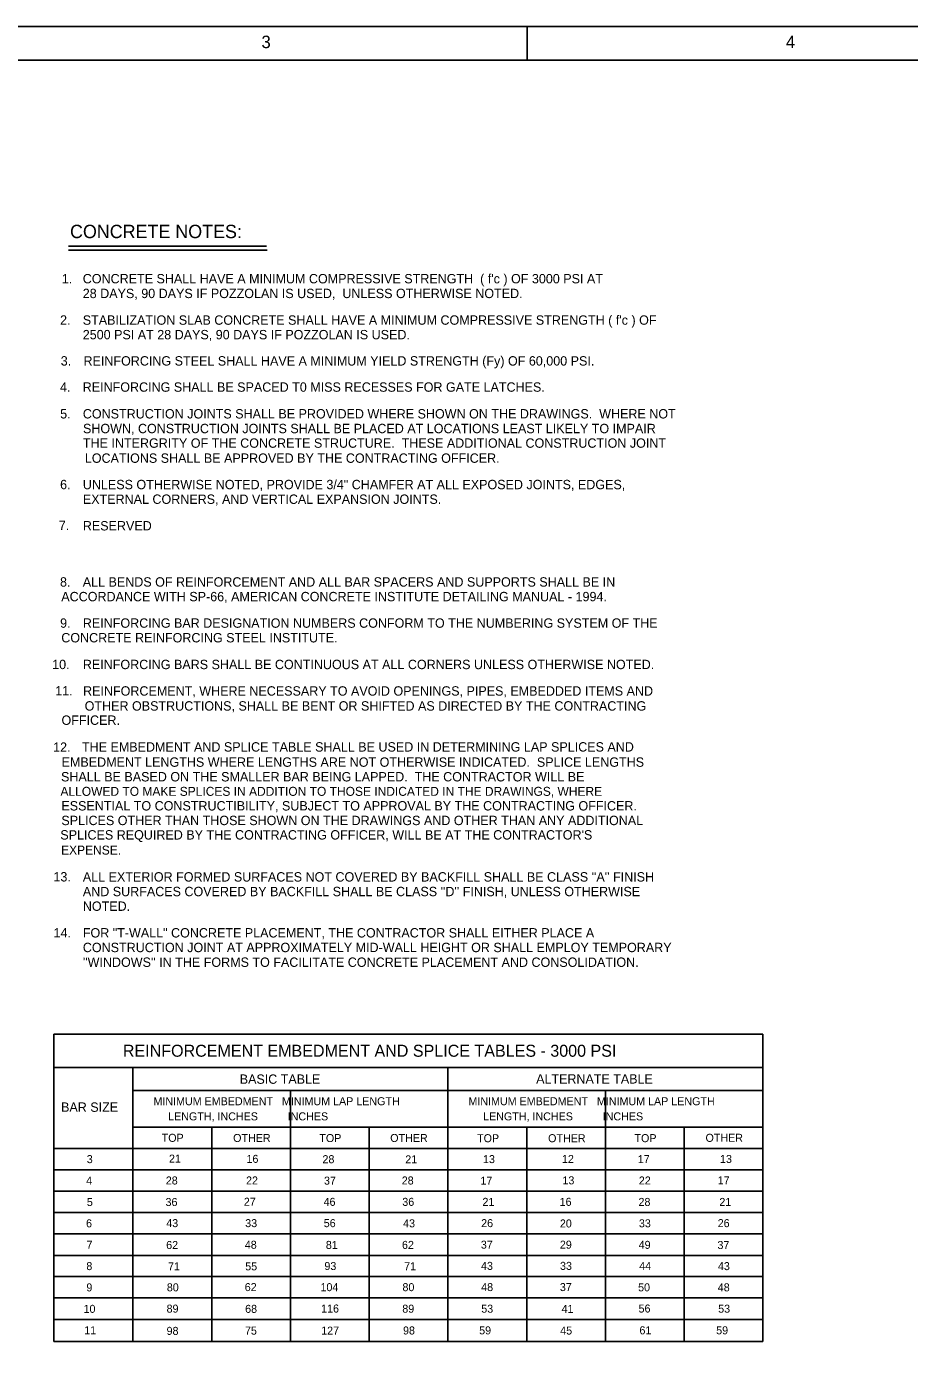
# Model space of a CAD drawing. Extents: x 22369.62 to 22373.29, y 22369.62 to 22372.46.
# Drawn here: x 22371.083 to 22372.185, y 22370.797 to 22372.455 of the extents above; entities that cross this region are included whole.
import ezdxf

# ---------------------------------------------------------------- set-up
doc = ezdxf.new("R2010")
doc.units = 0
for name, color, linetype in [('Level 1', 7, 'Continuous'), ('Level 10', 7, 'Continuous'), ('Level 2', 7, 'Continuous'), ('Level 3', 7, 'Continuous'), ('Level 4', 7, 'Continuous'), ('Level 7', 7, 'Continuous'), ('Level 9', 7, 'Continuous')]:
    doc.layers.add(name, color=color, linetype=linetype)

msp = doc.modelspace()

# ---------------------------------------------------------------- linework, layer by layer
at = {"layer": 'Level 1'}
for p, q in [((22372.0023, 22371.0269), (22371.1167, 22371.0269)), ((22372.0023, 22371.0001), (22371.1167, 22371.0001)), ((22372.0023, 22370.9735), (22371.1167, 22370.9735)), ((22372.0023, 22370.9467), (22371.1167, 22370.9467)), ((22372.0023, 22370.9198), (22371.1167, 22370.9198)), ((22372.0023, 22370.8934), (22371.1167, 22370.8934)), ((22372.0023, 22370.8668), (22371.1167, 22370.8668)), ((22372.0023, 22370.8399), (22371.1167, 22370.8399))]:
    msp.add_line(p, q, dxfattribs=at)
msp.add_lwpolyline([(22369.6213, 22372.4553), (22373.288, 22372.4553), (22373.288, 22369.6213), (22369.6213, 22369.6213)], close=True, dxfattribs=at)
at = {"layer": 'Level 10'}
for p, q in [((22371.708, 22372.4133), (22371.708, 22372.4553)), ((22371.1351, 22372.1807), (22371.3823, 22372.1807)), ((22371.1351, 22372.1757), (22371.383, 22372.1757)), ((22371.1167, 22370.8125), (22371.1167, 22371.1964)), ((22371.1167, 22371.1964), (22372.0023, 22371.1964)), ((22372.0023, 22370.8125), (22372.0023, 22371.1964)), ((22371.1167, 22371.1546), (22372.0023, 22371.1546)), ((22372.0023, 22370.8125), (22371.1167, 22370.8125))]:
    msp.add_line(p, q, dxfattribs=at)
at = {"layer": 'Level 2'}
for p, q in [((22371.2154, 22371.0802), (22372.0023, 22371.0802)), ((22371.3138, 22370.8125), (22371.3138, 22371.0802)), ((22371.5106, 22370.8125), (22371.5106, 22371.0802)), ((22371.7073, 22370.8125), (22371.7073, 22371.0802)), ((22371.904, 22370.8125), (22371.904, 22371.0802))]:
    msp.add_line(p, q, dxfattribs=at)
at = {"layer": 'Level 7'}
for p, q in [((22371.2154, 22370.8125), (22371.2154, 22371.1546)), ((22371.6089, 22370.8125), (22371.6089, 22371.1546)), ((22371.2154, 22371.1259), (22372.0023, 22371.1259)), ((22371.4122, 22370.8125), (22371.4122, 22371.1259)), ((22371.8056, 22370.8125), (22371.8056, 22371.1259)), ((22372.0023, 22371.0535), (22371.1167, 22371.0535))]:
    msp.add_line(p, q, dxfattribs=at)
at = {"layer": 'Level 9'}
msp.add_line((22369.7463, 22372.4133), (22373.017, 22372.4133), dxfattribs=at)

# ---------------------------------------------------------------- texts
at = {"layer": 'Level 1'}
for s, p in [('3', (22371.376, 22372.4283)), ('4', (22372.031, 22372.4283))]:
    msp.add_text(s, height=0.0156, dxfattribs=at).set_placement(p)
at = {"layer": 'Level 3'}
msp.add_text('CONCRETE NOTES:', height=0.016698, dxfattribs=at).set_placement((22371.1369, 22372.1909))
at = {"layer": 'Level 4'}
for s, height, p in [('1.', 0.0117, (22371.1267, 22372.1344)), ("CONCRETE SHALL HAVE A MINIMUM COMPRESSIVE STRENGTH  ( f'c ) OF 3000 PSI AT", 0.011698, (22371.1528, 22372.1344)), ('28 DAYS, 90 DAYS IF POZZOLAN IS USED,  UNLESS OTHERWISE NOTED.', 0.011698, (22371.1528, 22372.116)), ('2.', 0.0117, (22371.1245, 22372.0828)), ("STABILIZATION SLAB CONCRETE SHALL HAVE A MINIMUM COMPRESSIVE STRENGTH ( f'c ) OF", 0.011698, (22371.1528, 22372.0827)), ('2500 PSI AT 28 DAYS, 90 DAYS IF POZZOLAN IS USED.', 0.011698, (22371.1528, 22372.0645)), ('3.', 0.0117, (22371.1253, 22372.0317)), ('REINFORCING STEEL SHALL HAVE A MINIMUM YIELD STRENGTH (Fy) OF 60,000 PSI.', 0.011698, (22371.1537, 22372.0317)), ('4.', 0.0117, (22371.1244, 22371.999)), ('REINFORCING SHALL BE SPACED T0 MISS RECESSES FOR GATE LATCHES.', 0.011698, (22371.1527, 22371.999)), ('5.', 0.0117, (22371.1246, 22371.9656)), ('CONSTRUCTION JOINTS SHALL BE PROVIDED WHERE SHOWN ON THE DRAWINGS.  WHERE NOT', 0.011698, (22371.1529, 22371.9656)), ('SHOWN, CONSTRUCTION JOINTS SHALL BE PLACED AT LOCATIONS LEAST LIKELY TO IMPAIR', 0.011698, (22371.1531, 22371.9472)), ('THE INTERGRITY OF THE CONCRETE STRUCTURE.  THESE ADDITIONAL CONSTRUCTION JOINT', 0.011698, (22371.153, 22371.929)), ('LOCATIONS SHALL BE APPROVED BY THE CONTRACTING OFFICER.', 0.011698, (22371.1554, 22371.9102)), ('6.', 0.0117, (22371.1245, 22371.8772)), ('UNLESS OTHERWISE NOTED, PROVIDE 3/4" CHAMFER AT ALL EXPOSED JOINTS, EDGES,', 0.011698, (22371.1529, 22371.8772)), ('EXTERNAL CORNERS, AND VERTICAL EXPANSION JOINTS.', 0.011698, (22371.1529, 22371.8589)), ('7.', 0.0117, (22371.1229, 22371.8261)), ('RESERVED', 0.0117, (22371.1529, 22371.8257)), ('8.', 0.0117, (22371.1244, 22371.7555)), ('ALL BENDS OF REINFORCEMENT AND ALL BAR SPACERS AND SUPPORTS SHALL BE IN', 0.011698, (22371.1528, 22371.7555)), ('    ACCORDANCE WITH SP-66, AMERICAN CONCRETE INSTITUTE DETAILING MANUAL - 1994.', 0.011698, (22371.1086, 22371.7372)), ('9.', 0.0117, (22371.1245, 22371.7041)), ('REINFORCING BAR DESIGNATION NUMBERS CONFORM TO THE NUMBERING SYSTEM OF THE', 0.011698, (22371.1529, 22371.7041)), ('    CONCRETE REINFORCING STEEL INSTITUTE.', 0.011698, (22371.1086, 22371.6858)), ('10.', 0.0117, (22371.1146, 22371.6524)), ('REINFORCING BARS SHALL BE CONTINUOUS AT ALL CORNERS UNLESS OTHERWISE NOTED.', 0.011698, (22371.1529, 22371.6524)), ('11.', 0.0117, (22371.1184, 22371.6195)), ('REINFORCEMENT, WHERE NECESSARY TO AVOID OPENINGS, PIPES, EMBEDDED ITEMS AND', 0.011698, (22371.1532, 22371.6193)), ('OTHER OBSTRUCTIONS, SHALL BE BENT OR SHIFTED AS DIRECTED BY THE CONTRACTING', 0.011698, (22371.1552, 22371.6006)), ('    OFFICER.', 0.011698, (22371.1089, 22371.5828)), ('12.', 0.0117, (22371.1158, 22371.5491)), ('THE EMBEDMENT AND SPLICE TABLE SHALL BE USED IN DETERMINING LAP SPLICES AND', 0.011698, (22371.1518, 22371.5494)), ('    EMBEDMENT LENGTHS WHERE LENGTHS ARE NOT OTHERWISE INDICATED.  SPLICE LENGTHS', 0.011698, (22371.109, 22371.5304)), ('    SHALL BE BASED ON THE SMALLER BAR BEING LAPPED.  THE CONTRACTOR WILL BE', 0.011698, (22371.1083, 22371.5121)), ('    ALLOWED TO MAKE SPLICES IN ADDITION TO THOSE INDICATED IN THE DRAWINGS, WHERE', 0.0112, (22371.1083, 22371.4941)), ('    ESSENTIAL TO CONSTRUCTIBILITY, SUBJECT TO APPROVAL BY THE CONTRACTING OFFICER.', 0.011698, (22371.1087, 22371.4758)), ('    SPLICES OTHER THAN THOSE SHOWN ON THE DRAWINGS AND OTHER THAN ANY ADDITIONAL', 0.011698, (22371.1087, 22371.4575)), ("    SPLICES REQUIRED BY THE CONTRACTING OFFICER, WILL BE AT THE CONTRACTOR'S", 0.011698, (22371.1074, 22371.4395)), ('    EXPENSE.', 0.0112, (22371.1091, 22371.4207)), ('13.', 0.0117, (22371.1162, 22371.3871)), ("ALL EXTERIOR FORMED SURFACES NOT COVERED BY BACKFILL SHALL BE CLASS ''A'' FINISH", 0.011698, (22371.1529, 22371.387)), ("AND SURFACES COVERED BY BACKFILL SHALL BE CLASS ''D'' FINISH, UNLESS OTHERWISE", 0.011698, (22371.1529, 22371.3687)), ('NOTED.', 0.0117, (22371.1529, 22371.3504)), ('14.', 0.0117, (22371.1163, 22371.3171)), ('FOR "T-WALL" CONCRETE PLACEMENT, THE CONTRACTOR SHALL EITHER PLACE A', 0.011698, (22371.1529, 22371.3171)), ('CONSTRUCTION JOINT AT APPROXIMATELY MID-WALL HEIGHT OR SHALL EMPLOY TEMPORARY', 0.011698, (22371.1529, 22371.2988)), ("''WINDOWS'' IN THE FORMS TO FACILITATE CONCRETE PLACEMENT AND CONSOLIDATION.", 0.011698, (22371.1529, 22371.2804)), ('REINFORCEMENT EMBEDMENT AND SPLICE TABLES - 3000 PSI', 0.015, (22371.2029, 22371.1681)), ('BASIC TABLE', 0.011667, (22371.3489, 22371.1343)), ('ALTERNATE TABLE', 0.011667, (22371.7191, 22371.1346)), ('BAR SIZE', 0.0117, (22371.1257, 22371.0993)), ('MINIMUM EMBEDMENT   MINIMUM LAP LENGTH', 0.01, (22371.2411, 22371.1075)), ('MINIMUM EMBEDMENT   MINIMUM LAP LENGTH', 0.01, (22371.6345, 22371.1075)), ('LENGTH, INCHES          INCHES', 0.01, (22371.2594, 22371.0886)), ('LENGTH, INCHES          INCHES', 0.01, (22371.6528, 22371.0886)), ('TOP', 0.01, (22371.2514, 22371.0618)), ('OTHER', 0.01, (22371.3406, 22371.0616)), ('TOP', 0.01, (22371.4483, 22371.0615)), ('OTHER', 0.01, (22371.5368, 22371.0616)), ('TOP', 0.01, (22371.6453, 22371.0613)), ('OTHER', 0.01, (22371.734, 22371.0613)), ('TOP', 0.01, (22371.8419, 22371.0614)), ('OTHER', 0.01, (22371.9306, 22371.0618)), ('3', 0.01, (22371.1578, 22371.0352)), ('21', 0.01, (22371.2605, 22371.0358)), ('16', 0.01, (22371.3573, 22371.0355)), ('28', 0.01, (22371.4522, 22371.0351)), ('21', 0.01, (22371.5556, 22371.0349)), ('13', 0.01, (22371.6527, 22371.0352)), ('12', 0.01, (22371.7513, 22371.0354)), ('17', 0.01, (22371.846, 22371.0352)), ('13', 0.01, (22371.9487, 22371.0354)), ('4', 0.01, (22371.1571, 22371.0084)), ('28', 0.01, (22371.2565, 22371.0085)), ('22', 0.01, (22371.3567, 22371.0085)), ('37', 0.01, (22371.4541, 22371.0083)), ('28', 0.01, (22371.5512, 22371.0085)), ('17', 0.01, (22371.6495, 22371.0083)), ('13', 0.01, (22371.7519, 22371.0087)), ('22', 0.01, (22371.8473, 22371.0085)), ('17', 0.01, (22371.9458, 22371.0087)), ('5', 0.01, (22371.1579, 22370.9816)), ('36', 0.01, (22371.2562, 22370.9816)), ('27', 0.01, (22371.354, 22370.9819)), ('46', 0.01, (22371.4536, 22370.9818)), ('36', 0.01, (22371.5519, 22370.9818)), ('21', 0.01, (22371.652, 22370.9818)), ('16', 0.01, (22371.7484, 22370.9818)), ('28', 0.01, (22371.8469, 22370.9817)), ('21', 0.01, (22371.9479, 22370.9817)), ('6', 0.01, (22371.1569, 22370.955)), ('43', 0.01, (22371.2571, 22370.9552)), ('33', 0.01, (22371.3557, 22370.9552)), ('56', 0.01, (22371.4538, 22370.9552)), ('43', 0.01, (22371.5529, 22370.955)), ('26', 0.01, (22371.6504, 22370.9552)), ('20', 0.01, (22371.7487, 22370.9548)), ('33', 0.01, (22371.8474, 22370.955)), ('26', 0.01, (22371.9458, 22370.9552)), ('7', 0.01, (22371.1575, 22370.9282)), ('62', 0.01, (22371.257, 22370.9279)), ('48', 0.01, (22371.3552, 22370.9282)), ('81', 0.01, (22371.4564, 22370.928)), ('62', 0.01, (22371.5515, 22370.928)), ('37', 0.01, (22371.65, 22370.9283)), ('29', 0.01, (22371.7487, 22370.9283)), ('49', 0.01, (22371.8471, 22370.9281)), ('37', 0.01, (22371.9455, 22370.9279)), ('8', 0.01, (22371.1573, 22370.9015)), ('71', 0.01, (22371.2593, 22370.9012)), ('55', 0.01, (22371.3557, 22370.9012)), ('93', 0.01, (22371.4546, 22370.9016)), ('71', 0.01, (22371.5542, 22370.9014)), ('43', 0.01, (22371.6502, 22370.9018)), ('33', 0.01, (22371.7489, 22370.9018)), ('44', 0.01, (22371.8478, 22370.9017)), ('43', 0.01, (22371.9461, 22370.9015)), ('9', 0.01, (22371.1573, 22370.8749)), ('80', 0.01, (22371.2578, 22370.875)), ('62', 0.01, (22371.3551, 22370.8753)), ('104', 0.01, (22371.4497, 22370.8752)), ('80', 0.01, (22371.5521, 22370.8752)), ('48', 0.01, (22371.6504, 22370.8753)), ('37', 0.01, (22371.7487, 22370.8753)), ('50', 0.01, (22371.8464, 22370.875)), ('48', 0.01, (22371.9459, 22370.875)), ('10', 0.01, (22371.1538, 22370.8481)), ('89', 0.01, (22371.2575, 22370.8484)), ('68', 0.01, (22371.3556, 22370.8481)), ('116', 0.01, (22371.4505, 22370.8485)), ('89', 0.01, (22371.5519, 22370.8483)), ('53', 0.01, (22371.6505, 22370.8483)), ('41', 0.01, (22371.7508, 22370.8481)), ('56', 0.01, (22371.847, 22370.8485)), ('53', 0.01, (22371.9464, 22370.8483)), ('11', 0.01, (22371.1546, 22370.8213)), ('98', 0.01, (22371.2575, 22370.8206)), ('75', 0.01, (22371.3554, 22370.8209)), ('127', 0.01, (22371.4506, 22370.8209)), ('98', 0.01, (22371.5528, 22370.8211)), ('59', 0.01, (22371.6479, 22370.8212)), ('45', 0.01, (22371.7491, 22370.821)), ('61', 0.01, (22371.8481, 22370.8213)), ('59', 0.01, (22371.9439, 22370.8213))]:
    msp.add_text(s, height=height, dxfattribs=at).set_placement(p)

doc.saveas('drawing.dxf')
